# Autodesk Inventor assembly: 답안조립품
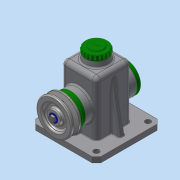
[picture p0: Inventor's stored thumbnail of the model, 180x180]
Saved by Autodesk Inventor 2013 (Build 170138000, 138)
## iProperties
Created: 2018-10
Part Number: 답안조립품
Document SubType Name: Assembly
Designer: Administrator
Author: Administrator
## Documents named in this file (14)
- C:\Users\Administrator\Desktop\481013V1017\답안조립품.iam
- C:\Users\Administrator\Desktop\481013V1017\본체.ipt
- C:\Users\Administrator\Desktop\481013V1017\V-벨트풀리.ipt
- C:\Users\Administrator\Desktop\481013V1017\뒤커버.ipt
- C:\Users\Administrator\Desktop\481013V1017\멈춤링 15 x 1.ipt
- C:\Users\Administrator\Desktop\481013V1017\베어링 15 x 35 x 11.ipt
- C:\Users\Administrator\Desktop\481013V1017\볼트 M4 x 10.ipt
- C:\Users\Administrator\Desktop\481013V1017\볼트 M6 x 12.ipt
- C:\Users\Administrator\Desktop\481013V1017\상부캡.ipt
- C:\Users\Administrator\Desktop\481013V1017\앞커버.ipt
- C:\Users\Administrator\Desktop\481013V1017\오일실 15 25 7.ipt
- C:\Users\Administrator\Desktop\481013V1017\와셔.ipt
- C:\Users\Administrator\Desktop\481013V1017\축.ipt
- C:\Users\Administrator\Desktop\481013V1017\키 5 x 5 x 14.ipt
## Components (1 placed, 1 different names)
1. V-벨트풀리:1
